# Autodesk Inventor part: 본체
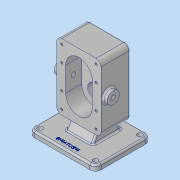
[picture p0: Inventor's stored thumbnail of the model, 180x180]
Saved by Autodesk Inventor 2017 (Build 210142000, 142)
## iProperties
Part Number: 본체
Material: 알루미늄 6061
Document SubType Name: Modeling
Designer: MRC
Density: 2.7 g/cm^3
Appearance: 알루미늄 - 평지
Mass: 1472.54 g
Surface Area: 818.394 cm^2
Volume: 545.387 cm^3
Author: MRC
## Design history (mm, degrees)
sketch "스케치1"
  geometry: L1 (-40, -60)-(40, -60); L2 (40, -60)-(40, 60); L3 (40, 60)-(-40, 60); L4 (-40, 60)-(-40, -60); L5 (-40, -60)-(40, 60); L6 (40, -60)-(-40, 60); 1 further point
  constraints: 12 end point, 2 midpoint, 2 parallel, 1 horizontal, 1 perpendicular
  dimensions: "d0" = 80 distance of L3.end L2.end; "d1" = 120 distance of L2.end L1.end
extrude "돌출1" new body sketch "스케치1" distance "d2" = 14; taper "d4" = 0 deg; dims "d3" = 39, "d5" = 0
sketch "스케치2"
  geometry: L1 (0, 22)-(0, -22); L2 (24, 22)-(24, -22); L3 (-24, -22)-(-24, 22); A1 r 24 centre (0, 22) between (24, 22) and (-24, 22); A2 r 24 centre (0, -22) between (-24, -22) and (24, -22); 2 further points
  constraints: 8 end point, 4 point on circle, 4 tangent, 2 centre point, 1 coincident, 1 midpoint, 1 parallel, 1 vertical
  dimensions: "d6" = 44 distance of L1.end L1.start; "d7" = 24 radius of A1
extrude "돌출2" cut sketch "스케치2" distance "d8" = 29; taper "d9" = 0 deg
sketch "스케치3"
  geometry: C1 r 12.5 at (0, -22); C2 r 12.5 at (0, 22); A1 r 24 centre (0, 22) between (24, 22) and (-24, 22) reference; A2 r 24 centre (0, -22) between (-24, -22) and (24, -22) reference; 1 further point
  constraints: 2 centre point, 2 coincident
  dimensions: "d10" = 25 diameter of C1; "d11" = 25 diameter of C2
extrude "돌출3" cut sketch "스케치3" distance "d12" = 15; taper "d13" = 0 deg
sketch "스케치4"
  geometry: C1 r 19 at (0, 22); A1 r 24 centre (0, 22) between (24, 22) and (-24, 22) reference; 1 further point
  constraints: 1 centre point, 1 coincident
  dimensions: "d14" = 38 diameter of C1
extrude "돌출4" join sketch "스케치4" distance "d15" = 17; taper "d16" = 0 deg
sketch "스케치5"
  geometry: L1 (9.5, -30)-(34.5, -30) reference; L2 (22, -30)-(22, -56); L3 (3, -56)-(41, -56) reference; L4 (36.404, -56)-(36, -55.3); L5 (36, -55.3)-(36, -48.7); L6 (36, -48.7)-(30.5, -48.7); L7 (30.5, -48.7)-(30.5, -30); L8 (30.5, -30)-(22, -30); L9 (36.404, -56)-(22, -56); 1 further point
  constraints: 14 end point, 2 collinear, 2 midpoint, 2 perpendicular, 2 point on line, 1 vertical
  dimensions: "d17" = 28 diameter of L5 L2; "d18" = 17 diameter of L7 L2; "d19" = 7.3 distance from line of L2.end L6; "d20" = 30 deg angle of L5 L4; "d21" = 0.7 vertical distance of L4.start L4.end
revolve "회전1" sketch "스케치5" stored, may be unused: angle "d22" = 90 deg
fillet "모깎기1" dims "d23" = 0.5
sketch "스케치6"
  geometry: L1 (-90, -56)-(-90, 44); L2 (3, -56)-(41, -56) reference; L3 (-90, 44)-(-80, 44); L4 (-80, 44)-(-80, -56); L5 (-80, -56)-(-90, -56); 1 further point
  constraints: 8 end point, 2 perpendicular, 1 horizontal, 1 horizontal alignment, 1 vertical
  dimensions: "d24" = 100 distance of L1.start L1.end; "d25" = 90 distance from line of point (0, 0) L1; "d26" = 10 distance of L1.end L3.end
extrude "돌출5" join sketch "스케치6" stored distance "d27" = 120; taper "d28" = 0 deg
fillet "모깎기2" dims "d29" = 10
sketch "스케치7"
  geometry: C1 r 4.5 at (0, 90); C2 r 4.5 at (0, 10); C3 r 4.5 at (100, 10); C4 r 4.5 at (100, 90); A1 r 10 centre (0, 90) between (0, 100) and (-10, 90) reference; A2 r 10 centre (0, 10) between (-10, 10) and (0, 0) reference; A3 r 10 centre (100, 10) between (100, 0) and (110, 10) reference; A4 r 10 centre (100, 90) between (110, 90) and (100, 100) reference; 1 further point
  constraints: 4 centre point, 4 coincident
  dimensions: "d30" = 9 diameter of C1; "d31" = 9 diameter of C2; "d32" = 9 diameter of C3; "d33" = 9 diameter of C4
extrude "돌출6" cut sketch "스케치7" stored distance "d34" = 120; taper "d35" = 0 deg
sketch "스케치9"
  geometry: L1 (-60, 2.453)-(-80, 14); L2 (-80, 14)-(-80, -39); L3 (-80, -39)-(-60, -27.453); L4 (-60, -27.453)-(-60, 2.453); L5 (-60, 14)-(-60, -39) reference; L6 (-80, 34)-(-80, -46) reference; L7 (-80, -56)-(-90, -56) reference; 1 further point
  constraints: 8 end point, 2 point on line, 1 parallel, 1 vertical
  dimensions: "d39" = 60 deg angle of L2 L3; "d40" = 60 deg angle of L2 L1; "d41" = 17 distance from line of L7 L2.end; "d42" = 53 distance of L1.end L2.end
extrude "돌출7" join sketch "스케치9" stored distance "d43" = 48; taper "d44" = 0 deg
sketch "스케치10"
  geometry: C1 r 11 at (14, 60); 1 further point
  constraints: 1 centre point, 1 coincident
  dimensions: "d45" = 22 diameter of C1
extrude "돌출8" join sketch "스케치10" distance "d46" = 8; taper "d47" = 0 deg
hole "구멍1" diameter "d50" = 8.376; stored, may be unused: countersink angle "d54" = 90 deg, drill point angle "d56" = 118 deg; dims "d48" = 10, "d49" = 10, "d51" = 96, "d52" = 10, "d53" = 7.3, "d55" = 27.3
fillet "모깎기3" dims "d57" = 9
sketch "스케치11"
  geometry: A1 r 9 centre (31, -51) between (31, -60) and (40, -51) reference; A2 r 9 centre (31, 51) between (40, 51) and (31, 60) reference; 5 further points
  constraints: 3 vertical alignment, 2 coincident
  dimensions: "d58" = 29 distance of point (31, 51) point (31, 22); "d59" = 44 distance of point (31, -22) point (31, 22)
hole "구멍2" sketch "스케치11" at (31, 51), (31, -51), (31, 22), (31, -22) diameter "d60" = 4.134; stored, may be unused: countersink angle "d64" = 90 deg, drill point angle "d66" = 118 deg; dims "d61" = 10, "d62" = 10, "d63" = 7.3, "d65" = 12
sketch "스케치12" dims "d0" = 80, "d1" = 120
  geometry: 4 further points
  constraints: 1 other
  dimensions: "d67" = 10 vertical distance of point (0, 0) point (50, 10); "d68" = 60 distance of point (-10, 10) point (50, 10)
feature "엠보싱1" sketch "스케치12" dims "d0" = 80, "d1" = 120, "d69" = 0.5, "d70" = 0
fillet "모깎기4" dims "d71" = 3
fillet "모깎기5" dims "d72" = 3
chamfer "모따기1" distance "d73" = 1; stored, may be unused: second distance "d74" = 2, angle "d75" = 45 deg
node "솔리드1"
mirror "미러1"
mirror "미러2"
